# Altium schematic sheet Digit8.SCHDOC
size A4 portrait; Organization: Altium Limited; Address1: L3, 12a Rodborough Rd; Address2: Frenchs Forest; Address3: NSW; Address4: Australia 2086; DocumentNumber: 2; SheetNumber: 2; SheetTotal: 6
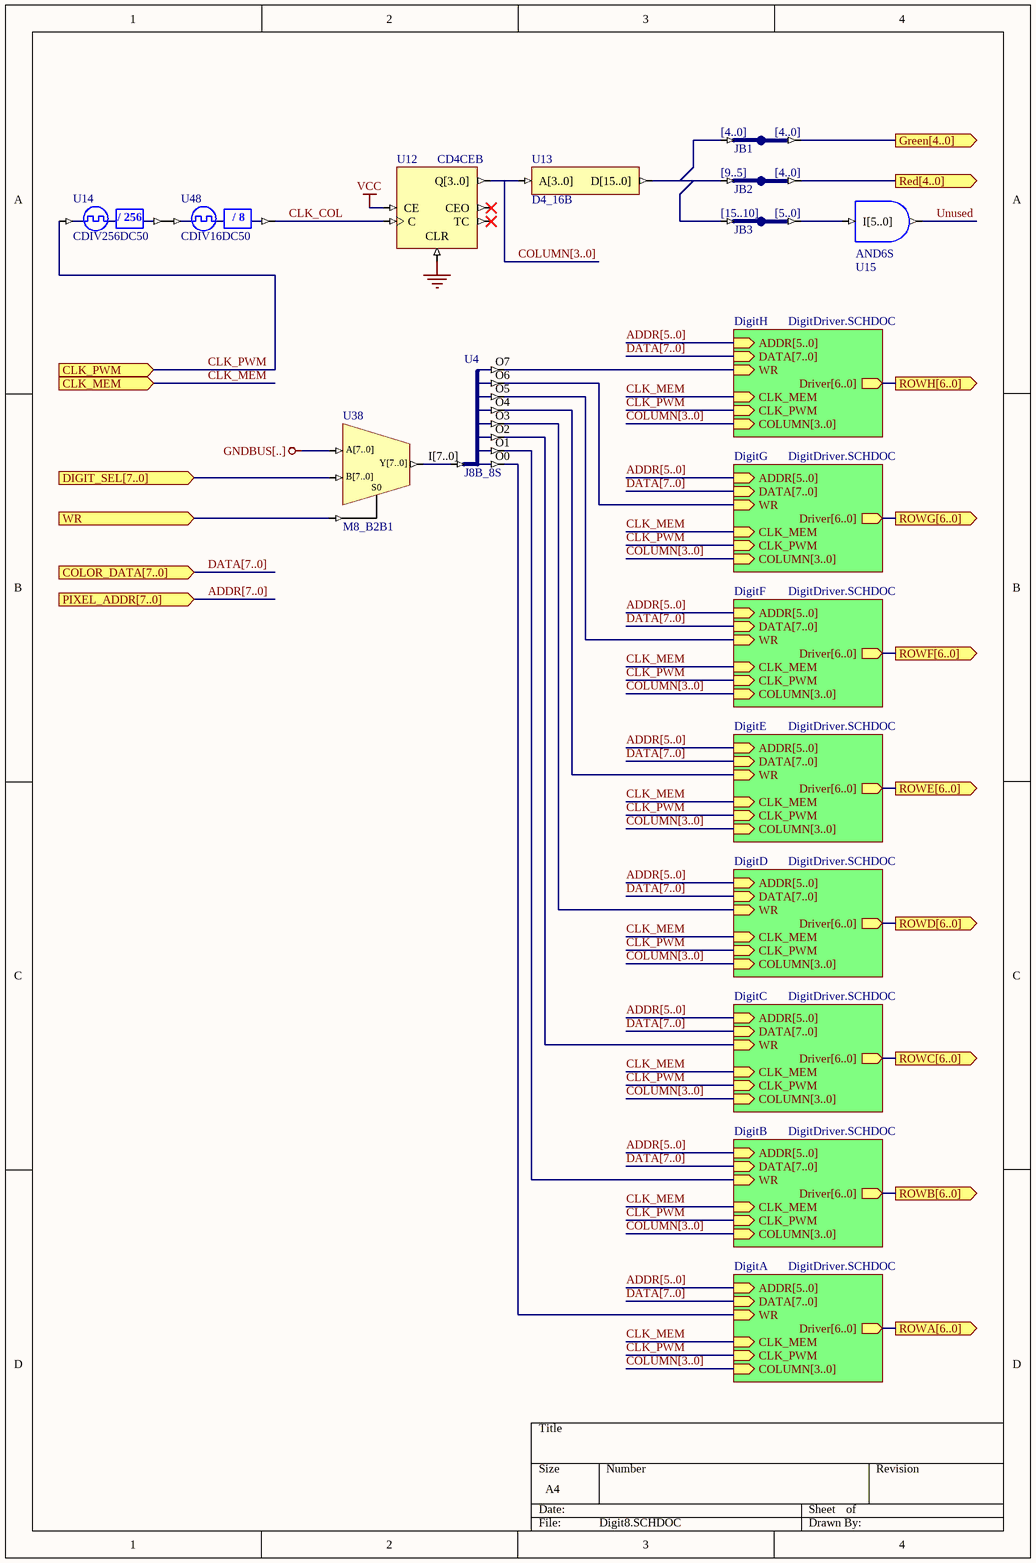
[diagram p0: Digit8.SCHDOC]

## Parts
JB1  IndexA: [4..0]  (hidden comment: JB)
JB2  IndexA: [9..5]  IndexB: [4..0]  (hidden comment: JB)
JB3  IndexA: [15..10]  IndexB: [5..0]  (hidden comment: JB)
U4  J8B_8S
U12  CD4CEB
U13  D4_16B
U14  CDIV256DC50
U15  AND6S
U38  M8_B2B1
U48  CDIV16DC50

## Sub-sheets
DigitA = DigitDriver.SCHDOC: COLUMN[3..0] (in), ADDR[5..0] (in), WR (in), DATA[7..0] (in), CLK_PWM (in), Driver[6..0] (out), CLK_MEM (in)
DigitB = DigitDriver.SCHDOC: COLUMN[3..0] (in), ADDR[5..0] (in), WR (in), DATA[7..0] (in), CLK_PWM (in), Driver[6..0] (out), CLK_MEM (in)
DigitC = DigitDriver.SCHDOC: COLUMN[3..0] (in), ADDR[5..0] (in), WR (in), DATA[7..0] (in), CLK_PWM (in), Driver[6..0] (out), CLK_MEM (in)
DigitD = DigitDriver.SCHDOC: COLUMN[3..0] (in), ADDR[5..0] (in), WR (in), DATA[7..0] (in), CLK_PWM (in), Driver[6..0] (out), CLK_MEM (in)
DigitE = DigitDriver.SCHDOC: COLUMN[3..0] (in), ADDR[5..0] (in), WR (in), DATA[7..0] (in), CLK_PWM (in), Driver[6..0] (out), CLK_MEM (in)
DigitF = DigitDriver.SCHDOC: COLUMN[3..0] (in), ADDR[5..0] (in), WR (in), DATA[7..0] (in), CLK_PWM (in), Driver[6..0] (out), CLK_MEM (in)
DigitG = DigitDriver.SCHDOC: COLUMN[3..0] (in), ADDR[5..0] (in), WR (in), DATA[7..0] (in), CLK_PWM (in), Driver[6..0] (out), CLK_MEM (in)
DigitH = DigitDriver.SCHDOC: COLUMN[3..0] (in), ADDR[5..0] (in), WR (in), DATA[7..0] (in), CLK_PWM (in), Driver[6..0] (out), CLK_MEM (in)

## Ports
CLK_MEM (in), CLK_PWM (in), COLOR_DATA[7..0] (in), DIGIT_SEL[7..0] (in), Green[4..0] (out), PIXEL_ADDR[7..0] (in), Red[4..0] (out), ROWA[6..0] (out), ROWB[6..0] (out), ROWC[6..0] (out), ROWD[6..0] (out), ROWE[6..0] (out), ROWF[6..0] (out), ROWG[6..0] (out), ROWH[6..0] (out), WR (in)

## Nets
GND: U12.CLR
VCC: U12.CE
CLK_COL: U12.C U48.CLKDV
CLK_MEM: port CLK_MEM, sheet DigitA/CLK_MEM, sheet DigitB/CLK_MEM, sheet DigitC/CLK_MEM, sheet DigitD/CLK_MEM, sheet DigitE/CLK_MEM, sheet DigitF/CLK_MEM, sheet DigitG/CLK_MEM, sheet DigitH/CLK_MEM
CLK_PWM: U14.CLKIN ; port CLK_PWM, sheet DigitA/CLK_PWM, sheet DigitB/CLK_PWM, sheet DigitC/CLK_PWM, sheet DigitD/CLK_PWM, sheet DigitE/CLK_PWM, sheet DigitF/CLK_PWM, sheet DigitG/CLK_PWM, sheet DigitH/CLK_PWM
Unused: U15.O
WR: U38.S0 ; port WR
NetU4_O0: U4.O0 ; sheet DigitA/WR
NetU4_O1: U4.O1 ; sheet DigitB/WR
NetU4_O2: U4.O2 ; sheet DigitC/WR
NetU4_O3: U4.O3 ; sheet DigitD/WR
NetU4_O4: U4.O4 ; sheet DigitE/WR
NetU4_O5: U4.O5 ; sheet DigitF/WR
NetU4_O6: U4.O6 ; sheet DigitG/WR
NetU4_O7: U4.O7 ; sheet DigitH/WR
NetU14_CLKDV: U14.CLKDV U48.CLKIN

Not connected (* = marked no-connect by the designer): JB1 A[0..0] B[0..0]; JB2 A[0..0] B[0..0]; JB3 A[0..0] B[0..0]; U4 I[7..0]; U12 CEO* Q[3..0] TC*; U13 A[3..0] D[15..0]; U15 I[5..0]; U38 A[7..0] B[7..0] Y[7..0]

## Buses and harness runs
bus ADDR[5..0] = sheet DigitA/ADDR[5..0]
bus ADDR[5..0] = sheet DigitB/ADDR[5..0]
bus ADDR[5..0] = sheet DigitC/ADDR[5..0]
bus ADDR[5..0] = sheet DigitD/ADDR[5..0]
bus ADDR[5..0] = sheet DigitE/ADDR[5..0]
bus ADDR[5..0] = sheet DigitF/ADDR[5..0]
bus ADDR[5..0] = sheet DigitG/ADDR[5..0]
bus ADDR[5..0] = sheet DigitH/ADDR[5..0]
bus ADDR[7..0] = port PIXEL_ADDR[7..0]
bus COLUMN[3..0]
bus COLUMN[3..0] = sheet DigitA/COLUMN[3..0]
bus COLUMN[3..0] = sheet DigitB/COLUMN[3..0]
bus COLUMN[3..0] = sheet DigitC/COLUMN[3..0]
bus COLUMN[3..0] = sheet DigitD/COLUMN[3..0]
bus COLUMN[3..0] = sheet DigitE/COLUMN[3..0]
bus COLUMN[3..0] = sheet DigitF/COLUMN[3..0]
bus COLUMN[3..0] = sheet DigitG/COLUMN[3..0]
bus COLUMN[3..0] = sheet DigitH/COLUMN[3..0]
bus DATA[7..0] = port COLOR_DATA[7..0]
bus DATA[7..0] = sheet DigitA/DATA[7..0]
bus DATA[7..0] = sheet DigitB/DATA[7..0]
bus DATA[7..0] = sheet DigitC/DATA[7..0]
bus DATA[7..0] = sheet DigitD/DATA[7..0]
bus DATA[7..0] = sheet DigitE/DATA[7..0]
bus DATA[7..0] = sheet DigitF/DATA[7..0]
bus DATA[7..0] = sheet DigitG/DATA[7..0]
bus DATA[7..0] = sheet DigitH/DATA[7..0]
bus port ROWA[6..0] = sheet DigitA/Driver[6..0]
bus port ROWB[6..0] = sheet DigitB/Driver[6..0]
bus port ROWC[6..0] = sheet DigitC/Driver[6..0]
bus port ROWD[6..0] = sheet DigitD/Driver[6..0]
bus port ROWE[6..0] = sheet DigitE/Driver[6..0]
bus port ROWF[6..0] = sheet DigitF/Driver[6..0]
bus port ROWG[6..0] = sheet DigitG/Driver[6..0]
bus port ROWH[6..0] = sheet DigitH/Driver[6..0]

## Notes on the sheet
- Labels drawn without touching a wire or pin: GNDBUS[..]

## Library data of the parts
JB1-JB3 = JB: System Joiner; ArchiveName: GENERIC
U4 = J8B_8S: 8-Bit input bus to 8 single pin outputs; ArchiveName: GENERIC
U12 = CD4CEB: 4-Bit Cascadable BCD Counter with Clock Enable and Asynchronous Clear, Bus Version; ArchiveName: GENERIC
U13 = D4_16B: Binary 4- to 16-Bit Decoder, Bus Version; ArchiveName: GENERIC
U14 = CDIV256DC50: Clock Divider by 256 with 50% Duty Cycle Output; ArchiveName: GENERIC
U15 = AND6B: 6-Input AND Gate, Bus Version; ArchiveName: GENERIC
U38 = M8_B2B1: 2x8-Bit Bus to 1x8-Bit Bus Multiplexer; ArchiveName: GENERIC
U48 = CDIV8DC50: Clock Divider by 8 with 50% Duty Cycle Output; ArchiveName: GENERIC; Xilinx Equivalent: CLK_DIV8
